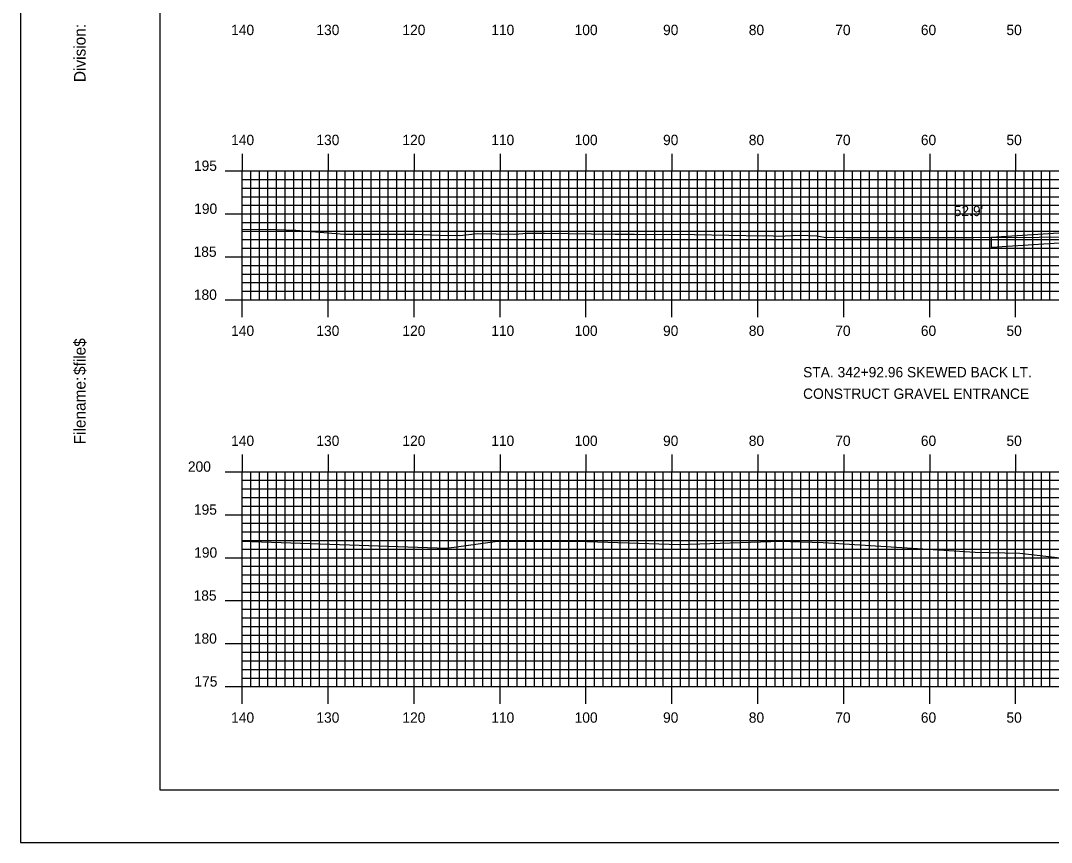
# Model space of a CAD drawing. Extents: x 1825147 to 1825490, y 442591 to 442811.
# Drawn here: x 1825146.6 to 1825266.5, y 442590.5 to 442686.2 of the extents above; entities that cross this region are included whole.
import ezdxf

# ---------------------------------------------------------------- set-up
doc = ezdxf.new("R2010")
doc.units = 0
for name, color, linetype in [('BORDER', 7, 'Continuous'), ('D_Roadway_FinishedGrade', 7, 'Continuous'), ('D_Text_Standard', 7, 'Continuous'), ('H_V ANNOTATION', 7, 'Continuous'), ('MAJOR', 7, 'Continuous'), ('MINOR', 7, 'Continuous'), ('PLOT BOUNDARY', 7, 'Continuous'), ('S_Roadway_Centerline', 7, 'Continuous')]:
    doc.layers.add(name, color=color, linetype=linetype)

msp = doc.modelspace()

# ---------------------------------------------------------------- linework, layer by layer
at = {"layer": 'BORDER'}
msp.add_lwpolyline([(1825162.76, 442596.67), (1825482.76, 442596.67), (1825482.76, 442806.67), (1825162.76, 442806.67)], close=True, dxfattribs=at)
at = {"layer": 'D_Roadway_FinishedGrade'}
msp.add_line((1825259.51, 442660.92), (1825259.51, 442659.76), dxfattribs=at)
for points in [[(1825291.51, 442662.2), (1825285.51, 442662.26), (1825279.51, 442662.2), (1825259.51, 442660.92)], [(1825282.53, 442661.07), (1825279.55, 442661.04), (1825259.59, 442659.76)]]:
    msp.add_lwpolyline(points, dxfattribs=at)
at = {"layer": 'MAJOR'}
for p, q in [((1825172.36, 442670.67), (1825172.36, 442668.67)), ((1825182.36, 442670.67), (1825182.36, 442668.67)), ((1825192.36, 442670.67), (1825192.36, 442668.67)), ((1825202.36, 442670.67), (1825202.36, 442668.67)), ((1825212.36, 442670.67), (1825212.36, 442668.67)), ((1825222.36, 442670.67), (1825222.36, 442668.67)), ((1825232.36, 442670.67), (1825232.36, 442668.67)), ((1825242.36, 442670.67), (1825242.36, 442668.67)), ((1825252.36, 442670.67), (1825252.36, 442668.67)), ((1825262.36, 442670.67), (1825262.36, 442668.67)), ((1825170.36, 442668.67), (1825172.36, 442668.67)), ((1825172.36, 442668.67), (1825312.36, 442668.67)), ((1825172.36, 442653.67), (1825172.36, 442668.67)), ((1825172.36, 442653.67), (1825172.36, 442668.67)), ((1825172.36, 442668.67), (1825312.36, 442668.67)), ((1825182.36, 442653.67), (1825182.36, 442668.67)), ((1825192.36, 442653.67), (1825192.36, 442668.67)), ((1825202.36, 442653.67), (1825202.36, 442668.67)), ((1825212.36, 442653.67), (1825212.36, 442668.67)), ((1825222.36, 442653.67), (1825222.36, 442668.67)), ((1825232.36, 442653.67), (1825232.36, 442668.67)), ((1825242.36, 442653.67), (1825242.36, 442668.67)), ((1825252.36, 442653.67), (1825252.36, 442668.67)), ((1825262.36, 442653.67), (1825262.36, 442668.67)), ((1825170.36, 442663.67), (1825172.36, 442663.67)), ((1825172.36, 442663.67), (1825312.36, 442663.67)), ((1825170.36, 442658.67), (1825172.36, 442658.67)), ((1825172.36, 442658.67), (1825312.36, 442658.67)), ((1825170.36, 442653.67), (1825172.36, 442653.67)), ((1825172.36, 442653.67), (1825312.36, 442653.67)), ((1825172.36, 442653.67), (1825312.36, 442653.67)), ((1825172.36, 442651.66), (1825172.36, 442653.67)), ((1825182.36, 442651.66), (1825182.36, 442653.67)), ((1825192.36, 442651.66), (1825192.36, 442653.67)), ((1825202.36, 442651.66), (1825202.36, 442653.67)), ((1825212.36, 442651.66), (1825212.36, 442653.67)), ((1825222.36, 442651.66), (1825222.36, 442653.67)), ((1825232.36, 442651.66), (1825232.36, 442653.67)), ((1825242.36, 442651.66), (1825242.36, 442653.67)), ((1825252.36, 442651.66), (1825252.36, 442653.67)), ((1825262.36, 442651.66), (1825262.36, 442653.67)), ((1825172.36, 442635.67), (1825172.36, 442633.67)), ((1825182.36, 442635.67), (1825182.36, 442633.67)), ((1825192.36, 442635.67), (1825192.36, 442633.67)), ((1825202.36, 442635.67), (1825202.36, 442633.67)), ((1825212.36, 442635.67), (1825212.36, 442633.67)), ((1825222.36, 442635.67), (1825222.36, 442633.67)), ((1825232.36, 442635.67), (1825232.36, 442633.67)), ((1825242.36, 442635.67), (1825242.36, 442633.67)), ((1825252.36, 442635.67), (1825252.36, 442633.67)), ((1825262.36, 442635.67), (1825262.36, 442633.67)), ((1825170.36, 442633.67), (1825172.36, 442633.67)), ((1825172.36, 442633.67), (1825452.36, 442633.67)), ((1825172.36, 442608.67), (1825172.36, 442633.67)), ((1825172.36, 442608.67), (1825172.36, 442633.67)), ((1825172.36, 442633.67), (1825452.36, 442633.67)), ((1825182.36, 442608.67), (1825182.36, 442633.67)), ((1825192.36, 442608.67), (1825192.36, 442633.67)), ((1825202.36, 442608.67), (1825202.36, 442633.67)), ((1825212.36, 442608.67), (1825212.36, 442633.67)), ((1825222.36, 442608.67), (1825222.36, 442633.67)), ((1825232.36, 442608.67), (1825232.36, 442633.67)), ((1825242.36, 442608.67), (1825242.36, 442633.67)), ((1825252.36, 442608.67), (1825252.36, 442633.67)), ((1825262.36, 442608.67), (1825262.36, 442633.67)), ((1825170.36, 442628.67), (1825172.36, 442628.67)), ((1825172.36, 442628.67), (1825452.36, 442628.67)), ((1825170.36, 442623.67), (1825172.36, 442623.67)), ((1825172.36, 442623.67), (1825452.36, 442623.67)), ((1825170.36, 442618.67), (1825172.36, 442618.67)), ((1825172.36, 442618.67), (1825452.36, 442618.67)), ((1825170.36, 442613.67), (1825172.36, 442613.67)), ((1825172.36, 442613.67), (1825452.36, 442613.67)), ((1825170.36, 442608.67), (1825172.36, 442608.67)), ((1825172.36, 442608.67), (1825452.36, 442608.67)), ((1825172.36, 442608.67), (1825452.36, 442608.67)), ((1825172.36, 442606.66), (1825172.36, 442608.67)), ((1825182.36, 442606.66), (1825182.36, 442608.67)), ((1825192.36, 442606.66), (1825192.36, 442608.67)), ((1825202.36, 442606.66), (1825202.36, 442608.67)), ((1825212.36, 442606.66), (1825212.36, 442608.67)), ((1825222.36, 442606.66), (1825222.36, 442608.67)), ((1825232.36, 442606.66), (1825232.36, 442608.67)), ((1825242.36, 442606.66), (1825242.36, 442608.67)), ((1825252.36, 442606.66), (1825252.36, 442608.67)), ((1825262.36, 442606.66), (1825262.36, 442608.67))]:
    msp.add_line(p, q, dxfattribs=at)
at = {"layer": 'MINOR'}
for p, q in [((1825173.36, 442653.67), (1825173.36, 442668.67)), ((1825174.36, 442653.67), (1825174.36, 442668.67)), ((1825175.36, 442653.67), (1825175.36, 442668.67)), ((1825176.36, 442653.67), (1825176.36, 442668.67)), ((1825177.36, 442653.67), (1825177.36, 442668.67)), ((1825178.36, 442653.67), (1825178.36, 442668.67)), ((1825179.36, 442653.67), (1825179.36, 442668.67)), ((1825180.36, 442653.67), (1825180.36, 442668.67)), ((1825181.36, 442653.67), (1825181.36, 442668.67)), ((1825183.36, 442653.67), (1825183.36, 442668.67)), ((1825184.36, 442653.67), (1825184.36, 442668.67)), ((1825185.36, 442653.67), (1825185.36, 442668.67)), ((1825186.36, 442653.67), (1825186.36, 442668.67)), ((1825187.36, 442653.67), (1825187.36, 442668.67)), ((1825188.36, 442653.67), (1825188.36, 442668.67)), ((1825189.36, 442653.67), (1825189.36, 442668.67)), ((1825190.36, 442653.67), (1825190.36, 442668.67)), ((1825191.36, 442653.67), (1825191.36, 442668.67)), ((1825193.36, 442653.67), (1825193.36, 442668.67)), ((1825194.36, 442653.67), (1825194.36, 442668.67)), ((1825195.36, 442653.67), (1825195.36, 442668.67)), ((1825196.36, 442653.67), (1825196.36, 442668.67)), ((1825197.36, 442653.67), (1825197.36, 442668.67)), ((1825198.36, 442653.67), (1825198.36, 442668.67)), ((1825199.36, 442653.67), (1825199.36, 442668.67)), ((1825200.36, 442653.67), (1825200.36, 442668.67)), ((1825201.36, 442653.67), (1825201.36, 442668.67)), ((1825203.36, 442653.67), (1825203.36, 442668.67)), ((1825204.36, 442653.67), (1825204.36, 442668.67)), ((1825205.36, 442653.67), (1825205.36, 442668.67)), ((1825206.36, 442653.67), (1825206.36, 442668.67)), ((1825207.36, 442653.67), (1825207.36, 442668.67)), ((1825208.36, 442653.67), (1825208.36, 442668.67)), ((1825209.36, 442653.67), (1825209.36, 442668.67)), ((1825210.36, 442653.67), (1825210.36, 442668.67)), ((1825211.36, 442653.67), (1825211.36, 442668.67)), ((1825213.36, 442653.67), (1825213.36, 442668.67)), ((1825214.36, 442653.67), (1825214.36, 442668.67)), ((1825215.36, 442653.67), (1825215.36, 442668.67)), ((1825216.36, 442653.67), (1825216.36, 442668.67)), ((1825217.36, 442653.67), (1825217.36, 442668.67)), ((1825218.36, 442653.67), (1825218.36, 442668.67)), ((1825219.36, 442653.67), (1825219.36, 442668.67)), ((1825220.36, 442653.67), (1825220.36, 442668.67)), ((1825221.36, 442653.67), (1825221.36, 442668.67)), ((1825223.36, 442653.67), (1825223.36, 442668.67)), ((1825224.36, 442653.67), (1825224.36, 442668.67)), ((1825225.36, 442653.67), (1825225.36, 442668.67)), ((1825226.36, 442653.67), (1825226.36, 442668.67)), ((1825227.36, 442653.67), (1825227.36, 442668.67)), ((1825228.36, 442653.67), (1825228.36, 442668.67)), ((1825229.36, 442653.67), (1825229.36, 442668.67)), ((1825230.36, 442653.67), (1825230.36, 442668.67)), ((1825231.36, 442653.67), (1825231.36, 442668.67)), ((1825233.36, 442653.67), (1825233.36, 442668.67)), ((1825234.36, 442653.67), (1825234.36, 442668.67)), ((1825235.36, 442653.67), (1825235.36, 442668.67)), ((1825236.36, 442653.67), (1825236.36, 442668.67)), ((1825237.36, 442653.67), (1825237.36, 442668.67)), ((1825238.36, 442653.67), (1825238.36, 442668.67)), ((1825239.36, 442653.67), (1825239.36, 442668.67)), ((1825240.36, 442653.67), (1825240.36, 442668.67)), ((1825241.36, 442653.67), (1825241.36, 442668.67)), ((1825243.36, 442653.67), (1825243.36, 442668.67)), ((1825244.36, 442653.67), (1825244.36, 442668.67)), ((1825245.36, 442653.67), (1825245.36, 442668.67)), ((1825246.36, 442653.67), (1825246.36, 442668.67)), ((1825247.36, 442653.67), (1825247.36, 442668.67)), ((1825248.36, 442653.67), (1825248.36, 442668.67)), ((1825249.36, 442653.67), (1825249.36, 442668.67)), ((1825250.36, 442653.67), (1825250.36, 442668.67)), ((1825251.36, 442653.67), (1825251.36, 442668.67)), ((1825253.36, 442653.67), (1825253.36, 442668.67)), ((1825254.36, 442653.67), (1825254.36, 442668.67)), ((1825255.36, 442653.67), (1825255.36, 442668.67)), ((1825256.36, 442653.67), (1825256.36, 442668.67)), ((1825257.36, 442653.67), (1825257.36, 442668.67)), ((1825258.36, 442653.67), (1825258.36, 442668.67)), ((1825259.36, 442653.67), (1825259.36, 442668.67)), ((1825260.36, 442653.67), (1825260.36, 442668.67)), ((1825261.36, 442653.67), (1825261.36, 442668.67)), ((1825263.36, 442653.67), (1825263.36, 442668.67)), ((1825264.36, 442653.67), (1825264.36, 442668.67)), ((1825265.36, 442653.67), (1825265.36, 442668.67)), ((1825266.36, 442653.67), (1825266.36, 442668.67)), ((1825172.36, 442667.67), (1825312.36, 442667.67)), ((1825172.36, 442667.67), (1825174.37, 442667.67)), ((1825172.36, 442666.67), (1825312.36, 442666.67)), ((1825172.36, 442666.67), (1825174.37, 442666.67)), ((1825172.36, 442665.67), (1825312.36, 442665.67)), ((1825172.36, 442665.67), (1825174.37, 442665.67)), ((1825172.36, 442664.67), (1825312.36, 442664.67)), ((1825172.36, 442664.67), (1825174.37, 442664.67)), ((1825172.36, 442662.67), (1825312.36, 442662.67)), ((1825172.36, 442662.67), (1825174.37, 442662.67)), ((1825172.36, 442661.67), (1825312.36, 442661.67)), ((1825172.36, 442661.67), (1825174.37, 442661.67)), ((1825172.36, 442660.67), (1825312.36, 442660.67)), ((1825172.36, 442660.67), (1825174.37, 442660.67)), ((1825172.36, 442659.67), (1825312.36, 442659.67)), ((1825172.36, 442659.67), (1825174.37, 442659.67)), ((1825172.36, 442657.67), (1825312.36, 442657.67)), ((1825172.36, 442657.67), (1825174.37, 442657.67)), ((1825172.36, 442656.67), (1825312.36, 442656.67)), ((1825172.36, 442656.67), (1825174.37, 442656.67)), ((1825172.36, 442655.67), (1825312.36, 442655.67)), ((1825172.36, 442655.67), (1825174.37, 442655.67)), ((1825172.36, 442654.67), (1825312.36, 442654.67)), ((1825172.36, 442654.67), (1825174.37, 442654.67)), ((1825173.36, 442608.67), (1825173.36, 442633.67)), ((1825174.36, 442608.67), (1825174.36, 442633.67)), ((1825175.36, 442608.67), (1825175.36, 442633.67)), ((1825176.36, 442608.67), (1825176.36, 442633.67)), ((1825177.36, 442608.67), (1825177.36, 442633.67)), ((1825178.36, 442608.67), (1825178.36, 442633.67)), ((1825179.36, 442608.67), (1825179.36, 442633.67)), ((1825180.36, 442608.67), (1825180.36, 442633.67)), ((1825181.36, 442608.67), (1825181.36, 442633.67)), ((1825183.36, 442608.67), (1825183.36, 442633.67)), ((1825184.36, 442608.67), (1825184.36, 442633.67)), ((1825185.36, 442608.67), (1825185.36, 442633.67)), ((1825186.36, 442608.67), (1825186.36, 442633.67)), ((1825187.36, 442608.67), (1825187.36, 442633.67)), ((1825188.36, 442608.67), (1825188.36, 442633.67)), ((1825189.36, 442608.67), (1825189.36, 442633.67)), ((1825190.36, 442608.67), (1825190.36, 442633.67)), ((1825191.36, 442608.67), (1825191.36, 442633.67)), ((1825193.36, 442608.67), (1825193.36, 442633.67)), ((1825194.36, 442608.67), (1825194.36, 442633.67)), ((1825195.36, 442608.67), (1825195.36, 442633.67)), ((1825196.36, 442608.67), (1825196.36, 442633.67)), ((1825197.36, 442608.67), (1825197.36, 442633.67)), ((1825198.36, 442608.67), (1825198.36, 442633.67)), ((1825199.36, 442608.67), (1825199.36, 442633.67)), ((1825200.36, 442608.67), (1825200.36, 442633.67)), ((1825201.36, 442608.67), (1825201.36, 442633.67)), ((1825203.36, 442608.67), (1825203.36, 442633.67)), ((1825204.36, 442608.67), (1825204.36, 442633.67)), ((1825205.36, 442608.67), (1825205.36, 442633.67)), ((1825206.36, 442608.67), (1825206.36, 442633.67)), ((1825207.36, 442608.67), (1825207.36, 442633.67)), ((1825208.36, 442608.67), (1825208.36, 442633.67)), ((1825209.36, 442608.67), (1825209.36, 442633.67)), ((1825210.36, 442608.67), (1825210.36, 442633.67)), ((1825211.36, 442608.67), (1825211.36, 442633.67)), ((1825213.36, 442608.67), (1825213.36, 442633.67)), ((1825214.36, 442608.67), (1825214.36, 442633.67)), ((1825215.36, 442608.67), (1825215.36, 442633.67)), ((1825216.36, 442608.67), (1825216.36, 442633.67)), ((1825217.36, 442608.67), (1825217.36, 442633.67)), ((1825218.36, 442608.67), (1825218.36, 442633.67)), ((1825219.36, 442608.67), (1825219.36, 442633.67)), ((1825220.36, 442608.67), (1825220.36, 442633.67)), ((1825221.36, 442608.67), (1825221.36, 442633.67)), ((1825223.36, 442608.67), (1825223.36, 442633.67)), ((1825224.36, 442608.67), (1825224.36, 442633.67)), ((1825225.36, 442608.67), (1825225.36, 442633.67)), ((1825226.36, 442608.67), (1825226.36, 442633.67)), ((1825227.36, 442608.67), (1825227.36, 442633.67)), ((1825228.36, 442608.67), (1825228.36, 442633.67)), ((1825229.36, 442608.67), (1825229.36, 442633.67)), ((1825230.36, 442608.67), (1825230.36, 442633.67)), ((1825231.36, 442608.67), (1825231.36, 442633.67)), ((1825233.36, 442608.67), (1825233.36, 442633.67)), ((1825234.36, 442608.67), (1825234.36, 442633.67)), ((1825235.36, 442608.67), (1825235.36, 442633.67)), ((1825236.36, 442608.67), (1825236.36, 442633.67)), ((1825237.36, 442608.67), (1825237.36, 442633.67)), ((1825238.36, 442608.67), (1825238.36, 442633.67)), ((1825239.36, 442608.67), (1825239.36, 442633.67)), ((1825240.36, 442608.67), (1825240.36, 442633.67)), ((1825241.36, 442608.67), (1825241.36, 442633.67)), ((1825243.36, 442608.67), (1825243.36, 442633.67)), ((1825244.36, 442608.67), (1825244.36, 442633.67)), ((1825245.36, 442608.67), (1825245.36, 442633.67)), ((1825246.36, 442608.67), (1825246.36, 442633.67)), ((1825247.36, 442608.67), (1825247.36, 442633.67)), ((1825248.36, 442608.67), (1825248.36, 442633.67)), ((1825249.36, 442608.67), (1825249.36, 442633.67)), ((1825250.36, 442608.67), (1825250.36, 442633.67)), ((1825251.36, 442608.67), (1825251.36, 442633.67)), ((1825253.36, 442608.67), (1825253.36, 442633.67)), ((1825254.36, 442608.67), (1825254.36, 442633.67)), ((1825255.36, 442608.67), (1825255.36, 442633.67)), ((1825256.36, 442608.67), (1825256.36, 442633.67)), ((1825257.36, 442608.67), (1825257.36, 442633.67)), ((1825258.36, 442608.67), (1825258.36, 442633.67)), ((1825259.36, 442608.67), (1825259.36, 442633.67)), ((1825260.36, 442608.67), (1825260.36, 442633.67)), ((1825261.36, 442608.67), (1825261.36, 442633.67)), ((1825263.36, 442608.67), (1825263.36, 442633.67)), ((1825264.36, 442608.67), (1825264.36, 442633.67)), ((1825265.36, 442608.67), (1825265.36, 442633.67)), ((1825266.36, 442608.67), (1825266.36, 442633.67)), ((1825172.36, 442632.67), (1825452.36, 442632.67)), ((1825172.36, 442632.67), (1825174.37, 442632.67)), ((1825172.36, 442631.67), (1825452.36, 442631.67)), ((1825172.36, 442631.67), (1825174.37, 442631.67)), ((1825172.36, 442630.67), (1825452.36, 442630.67)), ((1825172.36, 442630.67), (1825174.37, 442630.67)), ((1825172.36, 442629.67), (1825452.36, 442629.67)), ((1825172.36, 442629.67), (1825174.37, 442629.67)), ((1825172.36, 442627.67), (1825452.36, 442627.67)), ((1825172.36, 442627.67), (1825174.37, 442627.67)), ((1825172.36, 442626.67), (1825452.36, 442626.67)), ((1825172.36, 442626.67), (1825174.37, 442626.67)), ((1825172.36, 442625.67), (1825452.36, 442625.67)), ((1825172.36, 442625.67), (1825174.37, 442625.67)), ((1825172.36, 442624.67), (1825452.36, 442624.67)), ((1825172.36, 442624.67), (1825174.37, 442624.67)), ((1825172.36, 442622.67), (1825452.36, 442622.67)), ((1825172.36, 442622.67), (1825174.37, 442622.67)), ((1825172.36, 442621.67), (1825452.36, 442621.67)), ((1825172.36, 442621.67), (1825174.37, 442621.67)), ((1825172.36, 442620.67), (1825452.36, 442620.67)), ((1825172.36, 442620.67), (1825174.37, 442620.67)), ((1825172.36, 442619.67), (1825452.36, 442619.67)), ((1825172.36, 442619.67), (1825174.37, 442619.67)), ((1825172.36, 442617.67), (1825452.36, 442617.67)), ((1825172.36, 442617.67), (1825174.37, 442617.67)), ((1825172.36, 442616.67), (1825452.36, 442616.67)), ((1825172.36, 442616.67), (1825174.37, 442616.67)), ((1825172.36, 442615.67), (1825452.36, 442615.67)), ((1825172.36, 442615.67), (1825174.37, 442615.67)), ((1825172.36, 442614.67), (1825452.36, 442614.67)), ((1825172.36, 442614.67), (1825174.37, 442614.67)), ((1825172.36, 442612.67), (1825452.36, 442612.67)), ((1825172.36, 442612.67), (1825174.37, 442612.67)), ((1825172.36, 442611.67), (1825452.36, 442611.67)), ((1825172.36, 442611.67), (1825174.37, 442611.67)), ((1825172.36, 442610.67), (1825452.36, 442610.67)), ((1825172.36, 442610.67), (1825174.37, 442610.67)), ((1825172.36, 442609.67), (1825452.36, 442609.67)), ((1825172.36, 442609.67), (1825174.37, 442609.67))]:
    msp.add_line(p, q, dxfattribs=at)
at = {"layer": 'PLOT BOUNDARY'}
msp.add_lwpolyline([(1825146.57, 442590.55), (1825486.57, 442590.55), (1825486.57, 442810.55), (1825146.57, 442810.55)], close=True, dxfattribs=at)
at = {"layer": 'S_Roadway_Centerline'}
for points in [[(1825172.36, 442661.9), (1825176.32, 442661.84), (1825178.61, 442661.79), (1825180.42, 442661.63), (1825184.23, 442661.29), (1825187.91, 442661.29), (1825192.42, 442661.31), (1825194.38, 442661.22), (1825195.27, 442661.18), (1825197.67, 442661.15), (1825199.73, 442661.4), (1825204.08, 442661.32), (1825205.5, 442661.44), (1825207.55, 442661.41), (1825215.76, 442661.32), (1825218.02, 442661.31), (1825224.98, 442661.27), (1825233, 442661.13), (1825233.65, 442661.14), (1825234.73, 442661.06), (1825237.18, 442661.21), (1825239.24, 442661.11), (1825240.1, 442660.97), (1825242.63, 442660.94), (1825257.46, 442660.91), (1825265.09, 442660.95), (1825271.51, 442661.04)], [(1825172.36, 442625.6), (1825196.16, 442624.77), (1825202.05, 442625.61), (1825212.49, 442625.55), (1825223.23, 442625.2), (1825235.02, 442625.58), (1825236.14, 442625.56), (1825239.97, 442625.45), (1825257.67, 442624.33), (1825262.85, 442624.18), (1825268.56, 442623.55)]]:
    msp.add_lwpolyline(points, dxfattribs=at)

# ---------------------------------------------------------------- texts
at = {"layer": 'BORDER'}
for s, p in [('Division:', (1825154.13, 442679)), ('$file$', (1825154.13, 442644.92)), ('Filename:', (1825154.13, 442636.86))]:
    msp.add_text(s, height=1.339, rotation=90, dxfattribs=at).set_placement(p)
at = {"layer": 'D_Text_Standard'}
for s, p in [("52.9'", (1825255.16, 442663.41)), ('STA. 342+92.96 SKEWED BACK LT.', (1825237.63, 442644.65)), ('CONSTRUCT GRAVEL ENTRANCE', (1825237.63, 442642.15))]:
    msp.add_text(s, height=1.2, dxfattribs=at).set_placement(p)
at = {"layer": 'H_V ANNOTATION'}
for s, p in [('140', (1825171.07, 442684.47)), ('130', (1825180.99, 442684.47)), ('120', (1825191, 442684.47)), ('110', (1825201.34, 442684.47)), ('100', (1825211.04, 442684.47)), ('90', (1825221.33, 442684.47)), ('80', (1825231.31, 442684.47)), ('70', (1825241.37, 442684.47)), ('60', (1825251.33, 442684.47)), ('50', (1825261.29, 442684.47)), ('140', (1825171.07, 442671.67)), ('130', (1825180.99, 442671.67)), ('120', (1825191, 442671.67)), ('110', (1825201.34, 442671.67)), ('100', (1825211.04, 442671.67)), ('90', (1825221.33, 442671.67)), ('80', (1825231.31, 442671.67)), ('70', (1825241.37, 442671.67)), ('60', (1825251.33, 442671.67)), ('50', (1825261.29, 442671.67)), ('195', (1825166.74, 442668.67)), ('190', (1825166.77, 442663.67)), ('185', (1825166.7, 442658.67)), ('180', (1825166.73, 442653.67)), ('140', (1825171.07, 442649.47)), ('130', (1825180.99, 442649.47)), ('120', (1825191, 442649.47)), ('110', (1825201.34, 442649.47)), ('100', (1825211.04, 442649.47)), ('90', (1825221.33, 442649.47)), ('80', (1825231.31, 442649.47)), ('70', (1825241.37, 442649.47)), ('60', (1825251.33, 442649.47)), ('50', (1825261.29, 442649.47)), ('140', (1825171.07, 442636.67)), ('130', (1825180.99, 442636.67)), ('120', (1825191, 442636.67)), ('110', (1825201.34, 442636.67)), ('100', (1825211.04, 442636.67)), ('90', (1825221.33, 442636.67)), ('80', (1825231.31, 442636.67)), ('70', (1825241.37, 442636.67)), ('60', (1825251.33, 442636.67)), ('50', (1825261.29, 442636.67)), ('200', (1825166.04, 442633.67)), ('195', (1825166.74, 442628.67)), ('190', (1825166.77, 442623.67)), ('185', (1825166.7, 442618.67)), ('180', (1825166.73, 442613.67)), ('175', (1825166.8, 442608.67)), ('140', (1825171.07, 442604.47)), ('130', (1825180.99, 442604.47)), ('120', (1825191, 442604.47)), ('110', (1825201.34, 442604.47)), ('100', (1825211.04, 442604.47)), ('90', (1825221.33, 442604.47)), ('80', (1825231.31, 442604.47)), ('70', (1825241.37, 442604.47)), ('60', (1825251.33, 442604.47)), ('50', (1825261.29, 442604.47))]:
    msp.add_text(s, height=1.2, dxfattribs=at).set_placement(p)
at = {"layer": 'MAJOR'}
for p in [(1825172.35, 442653.67), (1825172.35, 442608.67)]:
    msp.add_text('-', height=0.012, dxfattribs=at).set_placement(p)

doc.saveas('drawing.dxf')
